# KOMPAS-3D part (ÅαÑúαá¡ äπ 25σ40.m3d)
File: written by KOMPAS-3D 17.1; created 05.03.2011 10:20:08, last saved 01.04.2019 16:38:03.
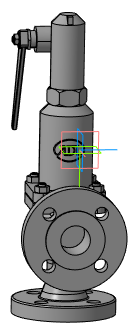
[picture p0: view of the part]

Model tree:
1. Операция без истории:1

Referenced files in C:\Users\tra\Desktop\Детали с марк. для Сферы\bsv\Desktop\Si 57\: VIC_496_25x40_3d.a3d
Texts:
  Viktor2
